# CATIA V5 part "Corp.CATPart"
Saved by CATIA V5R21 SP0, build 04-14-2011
Part number: Corp
Bounding box of the stored display mesh (mm): x -165 to 165, y 200 to 430, z -165 to 165
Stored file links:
  C:\Users\MIRCEA\Desktop\PRRO\CATIAV5\Corp.CATPart
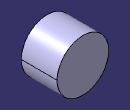
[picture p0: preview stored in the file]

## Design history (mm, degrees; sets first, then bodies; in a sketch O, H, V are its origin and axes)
Body1 (main body)
  Plane1: type Offset, RefPlane zx-plane, Offset 200
  Sketch1 on Plane1, origin (0, 200, 0), H (-1, 0, 0), V (0, 0, 1)
    circle A1 centre (0, 0) radius 165
    radius A1 = 165
  Pad1: profile Sketch1, direction (0, 1, 0), length 230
